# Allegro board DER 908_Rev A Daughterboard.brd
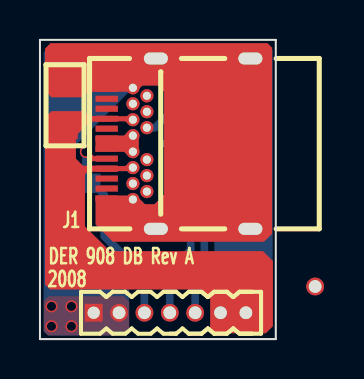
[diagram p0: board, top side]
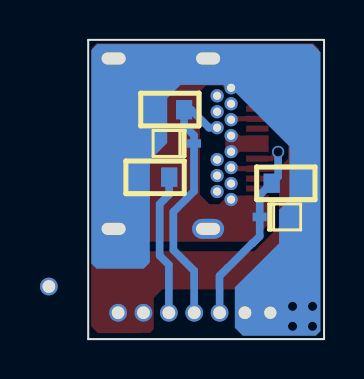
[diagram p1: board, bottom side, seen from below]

Outline 11.81 x 15 mm; copper layers: TOP, BOTTOM. Coordinates in mm from the lower left corner of the outline.
Outline path: 0,15 0,0 11.81,0 11.81,15 0,15

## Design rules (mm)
constraint set DEFAULT: min track width 0.508

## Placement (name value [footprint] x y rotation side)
C18  1 uF  [PISMC0805]  1.25 10.66 90 top
C19  560 pF  [PISMC0603]  2.62 7.82 180 bottom
C20  560 pF  [PISMC0603]  7.01 11.5 0 bottom
D4  MM3Z24VC  [PISMSOD323F]  3.22 6.12 180 bottom
D5  MM3Z24VC  [PISMSOD323F]  6.51 9.81 0 bottom
J1  CON24_USB_C  [PI_CONN_USBC_WURTH]  5.35 9.8 90 top
J3  CON8  [PI_HDR_1P27MM_8PIN]  2.69 1.32 0 top
NOREF  -  []  0 15 0 top
NOREF#2  -  []  -226.6 -145.28 0 top
NOREF#3  -  []  0 0 90 top
NOREF#4  -  []  -148.79 53.73 0 top
RT2  100 k  [PISMR0603]  9.17 8.12 180 bottom

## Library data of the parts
C18-C20 = CAP NP
D4 D5 = DIODE_ZENER
J1 = CON24_USB
J3 = CON8
RT2 = THERMISTOR

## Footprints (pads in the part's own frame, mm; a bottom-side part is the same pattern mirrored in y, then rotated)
PI_CONN_USBC_WURTH
  oval 1x1.6 hole 0.6x1.2: (-4.27,-0.45) (-4.27,-5.18) (4.27,-0.45) (4.27,-5.18)
  round 0.66 hole 0.406: (-2,0.7) (2,0.7) B1(2.8,0.7) B2(2.4,0) B3(1.6,0) B4(1.2,0.7) B5(0.8,0) B6(0.4,0.7) B7(-0.4,0.7) B8(-0.8,0) B9(-1.2,0.7) B10(-1.6,0) B11(-2.4,0) B12(-2.8,0.7)
  rect 0.305x1.118 smd: A1(-2.75,2.01) A2(-2.25,2.01) A3(-1.75,2.01) A4(-1.25,2.01) A5(-0.75,2.01) A6(-0.25,2.01) A7(0.25,2.01) A8(0.75,2.01) A9(1.25,2.01) A10(1.75,2.01) A11(2.25,2.01) A12(2.75,2.01)
PI_HDR_1P27MM_8PIN
  rect 0.889x0.889 hole 0.61: 1(0,0)
  round 0.889 hole 0.635: 2(1.27,0) 3(2.54,0) 4(3.81,0) 5(5.08,0) 6(6.35,0) 7(7.62,0) 8(11.088,1.316)
PISMC0603
  rect 0.813x0.965 smd: 1(0,0) 2(1.422,0)
PISMC0805
  rect 1.27x1.27 smd: 1(0,0) 2(2.134,0)
PISMR0603
  rect 0.813x0.965 smd: 1(0,0) 2(1.422,0)
PISMSOD323F
  rect 0.7x0.42 smd: 1(0,0) 2(2.5,0)

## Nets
VBUS: C18.1 J1.A4 J1.A9 J1.B4 J1.B9(VBUS4) J3.6 J3.7
CC1: C19.1 D4.1 J1.A5 J3.3
CC2: C20.1 D5.1 J1.B5 J3.4
NTC: J3.5 RT2.2
RTN: C18.2 C19.2 C20.2 D4.2 D5.2 J1.A1 J1.A12 J1.B1 J1.B12 J3.1 J3.2 RT2.1
N12665422: J1.A6 J1.A7 J1.B6 J1.B7

Pads without a net: J1 A2 A3 A8 A10 A11 B2 B3 B8 B10 B11; J3 8

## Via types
v1: diameter 0.61, hole 0.457, TOP to BOTTOM, 5 vias

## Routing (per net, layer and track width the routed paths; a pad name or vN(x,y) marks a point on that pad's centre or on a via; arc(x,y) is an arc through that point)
VBUS: length 2.7
  TOP w0.254: J1.B9 4.38,8.6 4.33,8.55 J1.A4 ; J1.B4 4.38,11 4.33,11.05 J1.A9
CC1: length 10.5
  TOP w0.254: v1(2.3,9.39) 2.64,9.05 J1.A5
  BOTTOM w0.381: v1(2.3,9.39) 2.3,8.14 C19.1 3.22,7.22 D4.1 3.22,5.15 3.57,4.8 3.59,4.8 5.23,3.17 J3.3
CC2: length 13.3
  BOTTOM w0.381: J1.B5 5.75,10.6 6.66,11.5 C20.1 7.01,10.71 6.51,10.21 D5.1 6.51,7.42 7.54,6.38 7.54,4.47 6.5,3.43 J3.4
NTC: length 7.2
  BOTTOM w0.381: RT2.2 7.75,7.25 8.23,6.77 8.23,4.19 7.77,3.73 J3.5
RTN:
  vias: v1(0.58,1.64) v1(0.58,0.64) v1(1.58,1.64) v1(1.58,0.64)

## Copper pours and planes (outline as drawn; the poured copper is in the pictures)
VBUS on TOP (solid shape): 2.45,11.18 3.55,11.18 3.55,10.9 2.51,10.9 1.8,10.19 1.8,9.05 2.15,8.69 3.81,8.69 3.91,8.59 3.91,8.43 3.87,8.39 2.38,8.39 2.25,8.26 2.25,5.65 3.5,4.41 3.5,4.41 11.16,4.41 11.66,3.91 11.66,0.65 11.31,0.3 9.12,0.3 9.11,0.31 8.71,0.31 8.52,0.5 8.52,2.06 8.1,2.49 0.51,2.49 0.26,2.74 0.26,11.1 0.58,11.43 2.21,11.43
RTN on TOP (solid shape): 11.62,14.6 11.62,5.29 11.22,4.88 3.65,4.88 2.79,5.75 2.79,7.2 4.82,7.2 5.25,6.76 5.73,6.76 6.22,7.25 6.22,12.4 5.91,12.71 5.12,12.71 4.82,12.4 2.37,12.4 2.1,12.12 0.58,12.12 0.26,12.45 0.26,14.56 0.53,14.83 11.39,14.83
RTN on BOTTOM (solid shape): 11.36,14.78 11.65,14.49 11.65,3.8 11.39,3.53 9.02,3.53 8.72,3.83 8.72,8.96 7.85,9.83 7.85,12.07 7.18,12.75 5.04,12.75 4.64,12.35 4.41,12.35 1.73,9.66 1.73,9.19 1.72,9.19 1.72,8.79 1.73,8.79 1.73,6.99 2.25,6.47 2.25,4.8 4.47,2.59 4.47,0.57 4.07,0.17 0.41,0.17 0.18,0.4 0.18,14.39 0.18,14.39 0.58,14.79 1.13,14.79 11.36,14.79
RTN on TOP: 4.18,2.15 4.47,1.87 4.47,0.57 4.07,0.17 0.41,0.17 0.18,0.4 0.18,1.89 0.44,2.15
N12665422 on TOP (solid shape): 4.95,10.31 4.95,9.29 4.79,9.14 4.46,9.14 4.21,9.39 2.79,9.39 2.79,10.2 4.21,10.2 4.49,10.48 4.77,10.48

Small or netless copper shapes (teardrops, artwork), in the pictures only: 2 on TOP

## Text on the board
Ref Des/Silkscreen Top: 2008 | DER 908 DB Rev A
PAGE_OUTLINE: 14.  FAB HOUSE LOGO,DATE CODE TO BE IN SILK SCREEN ONLY.DO NOT USE COPPER. | 13.  MATERIAL FR4 COPPER 2oz THICKNESS 0.062"
